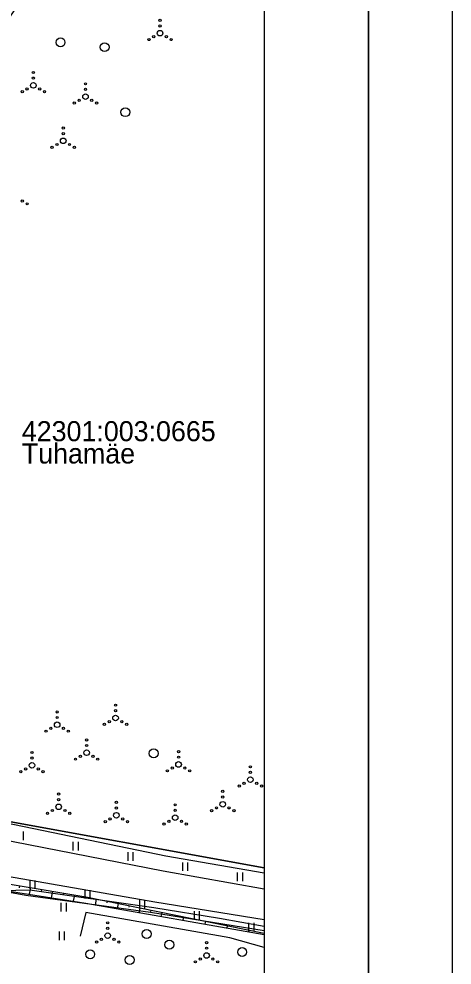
# Model space of a CAD drawing. Extents: x 599446 to 599962, y 6608194 to 6608886.
# Drawn here: x 599832.4 to 599871.3, y 6608574.6 to 6608659.5 of the extents above; entities that cross this region are included whole.
import ezdxf

# ---------------------------------------------------------------- set-up
doc = ezdxf.new("R2010")
doc.units = 0
for name, color, linetype in [('HALJASTUS', 7, 'Continuous'), ('MPKAABEL', 7, 'Continuous'), ('PIIR', 7, 'Continuous'), ('PR_SIDE', 7, 'Continuous'), ('RELJEEF', 7, 'Continuous'), ('TEE', 7, 'Continuous'), ('VORMISTUS_2', 7, 'Continuous')]:
    doc.layers.add(name, color=color, linetype=linetype)

msp = doc.modelspace()

# ---------------------------------------------------------------- linework, layer by layer
at = {"layer": 'HALJASTUS'}
for p, q in [((599832.833, 6608586.569), (599832.833, 6608585.808)), ((599837.292, 6608585.647), (599837.292, 6608584.886)), ((599837.747, 6608585.647), (599837.747, 6608584.886)), ((599842.206, 6608584.725), (599842.206, 6608583.964)), ((599842.661, 6608584.725), (599842.661, 6608583.964)), ((599847.121, 6608583.803), (599847.121, 6608583.042)), ((599847.576, 6608583.803), (599847.576, 6608583.042)), ((599852.039, 6608582.901), (599852.039, 6608582.14)), ((599852.494, 6608582.901), (599852.494, 6608582.14)), ((599833.419, 6608582.186), (599833.419, 6608581.425)), ((599833.874, 6608582.186), (599833.874, 6608581.425)), ((599838.346, 6608581.334), (599838.346, 6608580.573)), ((599838.801, 6608581.334), (599838.801, 6608580.573)), ((599836.212, 6608580.18), (599836.212, 6608579.419)), ((599836.667, 6608580.18), (599836.667, 6608579.419)), ((599843.266, 6608580.445), (599843.266, 6608579.683)), ((599843.721, 6608580.445), (599843.721, 6608579.683)), ((599848.163, 6608579.439), (599848.163, 6608578.678)), ((599848.619, 6608579.439), (599848.619, 6608578.678)), ((599853.054, 6608578.398), (599853.054, 6608577.637)), ((599853.509, 6608578.398), (599853.509, 6608577.637)), ((599836.043, 6608577.606), (599836.043, 6608576.845)), ((599836.499, 6608577.606), (599836.499, 6608576.845))]:
    msp.add_line(p, q, dxfattribs=at)
for points in [[(599854.437, 6608582.858), (599845.632, 6608584.378), (599826.804, 6608588.268), (599809.044, 6608591.586), (599807.451, 6608590.502), (599796.451, 6608594.999), (599793.207, 6608594.269), (599791.661, 6608599.006), (599795.433, 6608607.227), (599809.992, 6608629.503), (599824.333, 6608648.974), (599834.941, 6608664.558), (599840.035, 6608665.745), (599843.227, 6608674.906), (599844.956, 6608681.949), (599852.543, 6608691.108)], [(599854.437, 6608576.173), (599851.362, 6608577.045), (599838.459, 6608579.301), (599837.926, 6608577.206)]]:
    msp.add_lwpolyline(points, dxfattribs=at)
for centre, radius in [((599845.104, 6608659.356), 0.1), ((599845.104, 6608658.856), 0.1), ((599844.539, 6608657.881), 0.1), ((599845.104, 6608658.206), 0.25), ((599845.669, 6608657.881), 0.1), ((599836.174, 6608657.38), 0.4), ((599840.126, 6608656.948), 0.4), ((599844.104, 6608657.631), 0.1), ((599846.104, 6608657.631), 0.1), ((599833.738, 6608654.671), 0.1), ((599833.738, 6608653.521), 0.25), ((599833.738, 6608654.171), 0.1), ((599838.411, 6608653.656), 0.1), ((599832.738, 6608652.946), 0.1), ((599833.173, 6608653.196), 0.1), ((599834.303, 6608653.196), 0.1), ((599834.738, 6608652.946), 0.1), ((599838.411, 6608652.506), 0.25), ((599838.411, 6608653.156), 0.1), ((599837.411, 6608651.931), 0.1), ((599837.846, 6608652.181), 0.1), ((599838.976, 6608652.181), 0.1), ((599839.411, 6608651.931), 0.1), ((599841.987, 6608651.113), 0.4), ((599836.416, 6608649.691), 0.1), ((599836.416, 6608648.541), 0.25), ((599836.416, 6608649.191), 0.1), ((599835.416, 6608647.966), 0.1), ((599835.851, 6608648.216), 0.1), ((599836.981, 6608648.216), 0.1), ((599837.416, 6608647.966), 0.1), ((599832.742, 6608643.144), 0.1), ((599833.177, 6608642.894), 0.1), ((599841.111, 6608597.914), 0.1), ((599835.871, 6608597.308), 0.1), ((599835.871, 6608596.808), 0.1), ((599841.111, 6608596.764), 0.25), ((599841.111, 6608597.414), 0.1), ((599835.306, 6608595.833), 0.1), ((599835.871, 6608596.158), 0.25), ((599836.436, 6608595.833), 0.1), ((599840.111, 6608596.189), 0.1), ((599840.546, 6608596.439), 0.1), ((599841.676, 6608596.439), 0.1), ((599842.111, 6608596.189), 0.1), ((599834.871, 6608595.583), 0.1), ((599836.871, 6608595.583), 0.1), ((599838.516, 6608594.798), 0.1), ((599838.516, 6608594.298), 0.1), ((599833.609, 6608593.669), 0.1), ((599837.951, 6608593.323), 0.1), ((599838.516, 6608593.648), 0.25), ((599839.081, 6608593.323), 0.1), ((599844.533, 6608593.595), 0.4), ((599846.766, 6608593.748), 0.1), ((599846.766, 6608593.248), 0.1), ((599833.609, 6608592.519), 0.25), ((599833.609, 6608593.169), 0.1), ((599837.516, 6608593.073), 0.1), ((599839.516, 6608593.073), 0.1), ((599846.766, 6608592.598), 0.25), ((599853.213, 6608592.382), 0.1), ((599832.609, 6608591.944), 0.1), ((599833.044, 6608592.194), 0.1), ((599834.174, 6608592.194), 0.1), ((599834.609, 6608591.944), 0.1), ((599845.766, 6608592.023), 0.1), ((599846.201, 6608592.273), 0.1), ((599847.331, 6608592.273), 0.1), ((599847.766, 6608592.023), 0.1), ((599853.213, 6608591.882), 0.1), ((599852.648, 6608590.907), 0.1), ((599853.213, 6608591.232), 0.25), ((599853.778, 6608590.907), 0.1), ((599836.004, 6608589.944), 0.1), ((599850.732, 6608590.176), 0.1), ((599852.213, 6608590.657), 0.1), ((599854.213, 6608590.657), 0.1), ((599836.004, 6608589.444), 0.1), ((599841.185, 6608589.189), 0.1), ((599850.732, 6608589.026), 0.25), ((599850.732, 6608589.676), 0.1), ((599835.004, 6608588.219), 0.1), ((599835.439, 6608588.469), 0.1), ((599836.004, 6608588.794), 0.25), ((599836.569, 6608588.469), 0.1), ((599837.004, 6608588.219), 0.1), ((599841.185, 6608588.039), 0.25), ((599841.185, 6608588.689), 0.1), ((599846.462, 6608588.974), 0.1), ((599846.462, 6608588.474), 0.1), ((599849.732, 6608588.451), 0.1), ((599850.167, 6608588.701), 0.1), ((599851.297, 6608588.701), 0.1), ((599851.732, 6608588.451), 0.1), ((599840.185, 6608587.464), 0.1), ((599840.62, 6608587.714), 0.1), ((599841.75, 6608587.714), 0.1), ((599842.185, 6608587.464), 0.1), ((599845.897, 6608587.499), 0.1), ((599846.462, 6608587.824), 0.25), ((599847.027, 6608587.499), 0.1), ((599845.462, 6608587.249), 0.1), ((599847.462, 6608587.249), 0.1), ((599840.407, 6608578.388), 0.1), ((599840.407, 6608577.238), 0.25), ((599840.407, 6608577.888), 0.1), ((599843.905, 6608577.39), 0.4), ((599839.407, 6608576.663), 0.1), ((599839.842, 6608576.913), 0.1), ((599840.972, 6608576.913), 0.1), ((599841.407, 6608576.663), 0.1), ((599845.933, 6608576.426), 0.4), ((599849.28, 6608576.612), 0.1), ((599838.835, 6608575.563), 0.4), ((599849.28, 6608575.462), 0.25), ((599849.28, 6608576.112), 0.1), ((599852.474, 6608575.766), 0.4), ((599842.384, 6608575.056), 0.4), ((599848.28, 6608574.887), 0.1), ((599848.715, 6608575.137), 0.1), ((599849.845, 6608575.137), 0.1), ((599850.28, 6608574.887), 0.1)]:
    msp.add_circle(centre, radius, dxfattribs=at)
at = {"layer": 'MPKAABEL'}
msp.add_lwpolyline([(599782.282, 6608586.259), (599782.405, 6608586.985), (599783.936, 6608589.015), (599789.503, 6608588.678), (599800.41, 6608586.298), (599811.564, 6608584.757), (599822.594, 6608582.77), (599833.067, 6608580.884), (599844.238, 6608579.354), (599854.437, 6608577.709)], dxfattribs=at)
at = {"layer": 'PIIR'}
for points in [[(599854.437, 6608583.323), (599828.73, 6608587.98), (599817.31, 6608639.31), (599851.222, 6608691.108)], [(599746.81, 6608533.608), (599788.83, 6608594.82), (599828.73, 6608587.98), (599854.437, 6608583.323)]]:
    msp.add_lwpolyline(points, dxfattribs=at)
at = {"layer": 'PR_SIDE'}
msp.add_lwpolyline([(599780.528, 6608585.299), (599782.442, 6608587.336), (599785.44, 6608588.423), (599789.434, 6608588.181), (599795.884, 6608586.707), (599800.498, 6608586.791), (599811.643, 6608585.251), (599818.26, 6608584.116), (599825.524, 6608581.372), (599828.353, 6608581.236), (599833.433, 6608581.339), (599844.541, 6608579.758), (599850.447, 6608578.807), (599854.437, 6608578.085)], dxfattribs=at)
at = {"layer": 'RELJEEF'}
for p, q in [((599832.482, 6608581.713), (599832.451, 6608581.53)), ((599833.468, 6608581.548), (599833.368, 6608580.949)), ((599834.454, 6608581.382), (599834.425, 6608581.206)), ((599835.441, 6608581.217), (599835.344, 6608580.642)), ((599836.427, 6608581.052), (599836.399, 6608580.883)), ((599837.413, 6608580.887), (599837.321, 6608580.335)), ((599838.399, 6608580.721), (599838.372, 6608580.559)), ((599839.38, 6608580.524), (599839.276, 6608580.014)), ((599840.36, 6608580.324), (599840.33, 6608580.179)), ((599841.339, 6608580.125), (599841.246, 6608579.666)), ((599842.319, 6608579.925), (599842.293, 6608579.795)), ((599843.299, 6608579.726), (599843.216, 6608579.318)), ((599844.279, 6608579.526), (599844.256, 6608579.411)), ((599845.259, 6608579.327), (599845.186, 6608578.97)), ((599846.239, 6608579.127), (599846.219, 6608579.028)), ((599847.219, 6608578.928), (599847.156, 6608578.622)), ((599848.199, 6608578.728), (599848.182, 6608578.644)), ((599849.179, 6608578.529), (599849.127, 6608578.273)), ((599850.158, 6608578.329), (599850.144, 6608578.26)), ((599851.138, 6608578.129), (599851.097, 6608577.925)), ((599852.118, 6608577.93), (599852.107, 6608577.876)), ((599853.098, 6608577.73), (599853.067, 6608577.577)), ((599854.078, 6608577.531), (599854.07, 6608577.493))]:
    msp.add_line(p, q, dxfattribs=at)
for points in [[(599738.503, 6608533.608), (599747.576, 6608546.588), (599763.358, 6608570.259), (599776.504, 6608588.973), (599778.685, 6608590.228), (599780.974, 6608590.85), (599782.591, 6608590.668), (599789.068, 6608589.811), (599801.004, 6608587.052), (599825.729, 6608582.845), (599838.459, 6608580.711), (599854.437, 6608577.458)], [(599743.905, 6608533.608), (599750.951, 6608543.213), (599767.627, 6608567.644), (599779.48, 6608586.231), (599782.154, 6608588.41), (599783.352, 6608588.883), (599788.843, 6608588.633), (599800.848, 6608586.447), (599825.652, 6608582.147), (599838.441, 6608580.161), (599854.437, 6608577.335)]]:
    msp.add_lwpolyline(points, dxfattribs=at)
at = {"layer": 'TEE'}
for points in [[(599854.437, 6608581.395), (599845.399, 6608583.02), (599826.526, 6608586.694), (599801.842, 6608591.113), (599789.613, 6608594.125), (599786.413, 6608596.947), (599784.756, 6608598.98), (599784.301, 6608601.825), (599784.669, 6608604.283), (599790.786, 6608613.879), (599804.071, 6608634.135), (599817.047, 6608653.619), (599838.859, 6608686.624), (599841.837, 6608691.108)], [(599854.437, 6608578.651), (599844.624, 6608580.251), (599826.075, 6608583.474), (599801.334, 6608588.138), (599788.813, 6608590.962), (599783.359, 6608592.522), (599779.225, 6608592.079), (599775.664, 6608590.875), (599762.015, 6608571.264), (599745.769, 6608547.626), (599736.468, 6608533.608)]]:
    msp.add_lwpolyline(points, dxfattribs=at)
at = {"layer": 'VORMISTUS_2'}
for points in [[(599713.812, 6608728.608), (599871.312, 6608728.608), (599871.312, 6608505.858), (599713.812, 6608505.858)], [(599721.312, 6608514.108), (599863.812, 6608514.108), (599863.812, 6608720.358), (599721.312, 6608720.358)], [(599721.312, 6608720.358), (599863.812, 6608720.358), (599863.812, 6608514.108), (599721.312, 6608514.108)], [(599854.437, 6608533.608), (599730.687, 6608533.608), (599730.687, 6608691.108), (599854.437, 6608691.108)]]:
    msp.add_lwpolyline(points, close=True, dxfattribs=at)

# ---------------------------------------------------------------- texts
at = {"layer": 'PIIR'}
for s, p in [('42301:003:0665', (599832.697, 6608621.596)), ('Tuhamäe', (599832.697, 6608619.596))]:
    msp.add_text(s, height=1.8, dxfattribs=at).set_placement(p)

doc.saveas('drawing.dxf')
